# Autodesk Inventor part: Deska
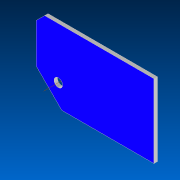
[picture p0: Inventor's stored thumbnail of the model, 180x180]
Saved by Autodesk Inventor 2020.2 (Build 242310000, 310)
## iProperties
Created: 2021-01
Part Number: Deska
Material: Všeobecné
Document SubType Name: Modeling
Designer: Pavel
Density: 1 g/cm^3
Appearance: Výchozí
UlozenoKym: navara
LastSaveDate: 12.01.2021
Author: Pavel
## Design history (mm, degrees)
sketch "Náčrt1"
  geometry: L1 (15, 0)-(69, 0); L2 (69, 0)-(69, 43); L3 (69, 43)-(5, 43); L4 (0, 38)-(0, 15); L5 (0, 15)-(15, 0); L6 (0, 38)-(5, 43); C1 r 2.5 at (13, 13); 1 further point
  constraints: 12 end point, 2 parallel, 1 centre point, 1 horizontal, 1 perpendicular
  dimensions: "d1" = 45 deg angle of L1 L5; "d3" = 5 diameter of C1
extrude "Vysunutí1" new body sketch "Náčrt1" distance "d4" = 2; taper "d5" = 0 deg
node "Pracovní osa1"
node "Těleso1"
